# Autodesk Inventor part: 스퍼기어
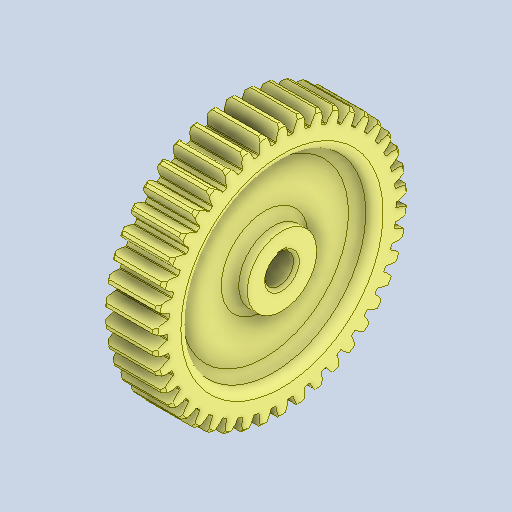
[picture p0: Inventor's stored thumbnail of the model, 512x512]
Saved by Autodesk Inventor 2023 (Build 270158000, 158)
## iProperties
Created: 2024-09
Part Number: 스퍼기어
Material: 강철, 탄소
Document SubType Name: Modeling
Designer: home
Density: 7.85 g/cm^3
Appearance: 기본값
Author: jhkim
Sending System: Autodesk Inventor 2025
Preprocessor: ST-DEVELOPER v20
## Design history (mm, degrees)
node "스퍼 기어1"
node "솔리드2"
node "솔리드1"
